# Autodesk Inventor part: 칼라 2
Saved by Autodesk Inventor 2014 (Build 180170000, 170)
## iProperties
Created: 2025-12
Part Number: 칼라 2
Material: 일반
Document SubType Name: Modeling
Designer: dg
Density: 1 g/cm^3
Appearance: 기본값
Author: dg
Author: jhkim
Creation Date: 2025-11-19
Sending System: Autodesk Inventor 2026
Preprocessor: ST-DEVELOPER v20.1
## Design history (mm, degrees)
node "칼라 21"
node "솔리드1"
node "기준1"
